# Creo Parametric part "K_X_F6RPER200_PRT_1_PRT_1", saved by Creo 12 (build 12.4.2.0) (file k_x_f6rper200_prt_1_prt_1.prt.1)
Units: Custom; MM, KILOGRAM, SECS

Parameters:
  PTC_WM_ITERATION = "0"
  PTC_WM_VERSION = "-.0"
  PTC_WM_LIFECYCLE_STATE = "In Work"
  PTC_WM_LIFECYCLE = "MO_CADDocument"
  PTC_WM_CREATED_BY = "Maximilian Roepper (Z0017RMS: MO)"
  PTC_WM_CREATED_ON = "18-Sep-26 11:36:42 AM"
  PTC_WM_MODIFIED_BY = "Maximilian Roepper (Z0017RMS: MO)"
  PTC_WM_MODIFIED_ON = "18-Sep-26 11:36:46 AM"
  PDMLINKNUMBER = "PDM000071454836"
  PTC_WM_NAME = "k_x_f6rper200_prt_1_prt_1.prt"
  PTC_WM_NUMBER = "PDM000071454836"

Other parameters: WEIGHT, WEIGHT_FACTOR, WEIGHT_ADD, _MASS_TEMP, _DIFF_TEMP, MC_ERRORS, SUPPLIER

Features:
  1. coordinate system
  2. datum plane "PRT_YZ"
  3. datum plane "PRT_XY"
  4. datum plane "PRT_XZ"
  5. coordinate system
  6. datum axis
  7. datum axis
  8. datum axis
  9. coordinate system
  10. imported feature
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
Other named items: PRT, SIEMENS_MO, DRW_VIEW_ORG, PRT_X, PRT_Y, PRT_Z, CS0, ROUGH_GROB

Layers: 00_STD_CSYS-KSYS, 01_STD_PLANES-EBENEN, 02_STD_AXES-ACHSEN, 03_STD_CSYS-KSYS, 24_IMPORT_FEAT-IMPORT_KE

Surfaces: 14 plane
